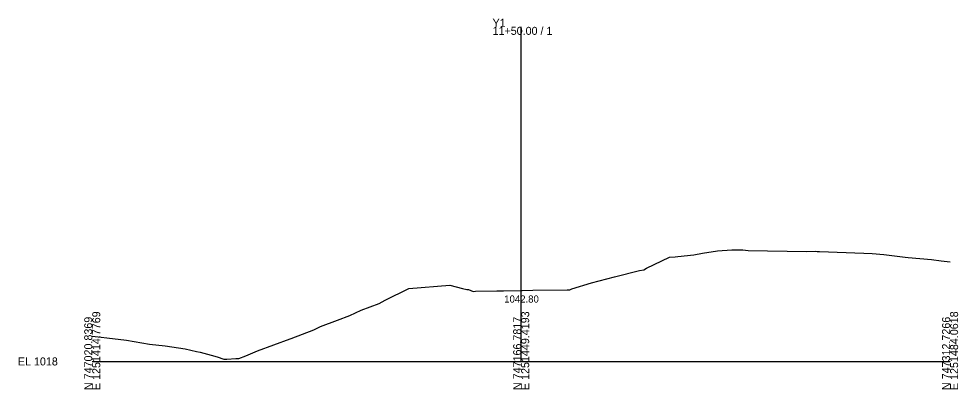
# Model space of a CAD drawing. Extents: x -76 to 353, y -258 to 1620.
# Drawn here: x 24.3 to 352.8, y 1490.3 to 1619.7 of the extents above; entities that cross this region are included whole.
import ezdxf

# ---------------------------------------------------------------- set-up
doc = ezdxf.new("R2010")
doc.units = 0
for name, color, linetype in [('Exist Cross Section Cell', 7, 'Continuous'), ('Exist XS Center Line Elevation Label', 7, 'Continuous'), ('Exist XS Ground Line', 7, 'Continuous')]:
    doc.layers.add(name, color=color, linetype=linetype)

msp = doc.modelspace()

# ---------------------------------------------------------------- linework, layer by layer
at = {"layer": 'Exist Cross Section Cell'}
for p, q in [((200, 1500), (200, 1616.86)), ((50, 1500), (200, 1500)), ((200, 1500), (350, 1500))]:
    msp.add_line(p, q, dxfattribs=at)
at = {"layer": 'Exist XS Ground Line'}
msp.add_lwpolyline([(50, 1508.82), (53.07, 1508.47), (55.09, 1508.23), (62, 1507.41), (69.97, 1506.02), (75.45, 1505.47), (82.51, 1504.43), (86.48, 1503.47), (87.7, 1503.2), (91.63, 1502.15), (93.73, 1501.63), (96.01, 1500.81), (97.07, 1500.78), (100.21, 1501.02), (101.21, 1501.02), (103.68, 1501.93), (107.77, 1503.71), (119.17, 1507.84), (119.51, 1507.97), (127.48, 1511.05), (129.79, 1512.23), (135.78, 1514.36), (140.07, 1516), (144.09, 1517.88), (150.35, 1520.25), (152.4, 1521.34), (160.71, 1525.42), (175.02, 1526.59), (179.48, 1525.42), (181.03, 1525.16), (181.53, 1525.14), (182.41, 1524.8), (183.2, 1524.46), (184.01, 1524.49), (191.48, 1524.6), (193.86, 1524.64), (200, 1524.8), (200.36, 1524.81), (204.05, 1524.89), (216.13, 1525.02), (217.02, 1524.98), (217.77, 1525.38), (224.62, 1527.44), (232.58, 1529.51), (241.37, 1531.74), (242.86, 1532), (243.78, 1532.53), (251.82, 1536.38), (253.88, 1536.55), (254.79, 1536.68), (260.39, 1537.28), (263.42, 1537.77), (268.7, 1538.64), (273.7, 1538.95), (277.55, 1538.93), (279.33, 1538.78), (299.75, 1538.43), (303.06, 1538.46), (303.47, 1538.45), (304.29, 1538.41), (319.86, 1537.87), (322.8, 1537.66), (326.85, 1537.4), (334.26, 1536.45), (335.37, 1536.3), (343.47, 1535.56), (346.88, 1535.14), (350, 1534.75)], dxfattribs=at)

# ---------------------------------------------------------------- texts
at = {"layer": 'Exist Cross Section Cell'}
for s, p in [('Y1', (190, 1616.86)), ('11+50.00 / 1', (190, 1614.06)), ('EL 1018', (24, 1498.6))]:
    msp.add_text(s, height=2.8, dxfattribs=at).set_placement(p)
for s, p in [('N 747020.8369', (50, 1490)), ('E 1251414.7769', (52.8, 1490)), ('N 747166.7817', (200, 1490)), ('E 1251449.4193', (202.8, 1490)), ('N 747312.7266', (350, 1490)), ('E 1251484.0618', (352.8, 1490))]:
    msp.add_text(s, height=2.8, rotation=90, dxfattribs=at).set_placement(p)
at = {"layer": 'Exist XS Center Line Elevation Label'}
msp.add_text('1042.80', height=2.5, dxfattribs=at).set_placement((194.08, 1520.55))

doc.saveas('drawing.dxf')
